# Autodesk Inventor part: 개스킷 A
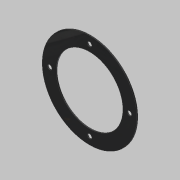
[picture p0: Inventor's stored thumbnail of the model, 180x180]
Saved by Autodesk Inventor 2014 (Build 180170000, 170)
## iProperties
Created: 2019-10
Part Number: 개스킷 A
Material: 고무
Document SubType Name: Modeling
Designer: mduedu
Density: 1 g/cm^3
Appearance: Rubber - Black - Version 1.1
Author: mduedu
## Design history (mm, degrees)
sketch "스케치1"
  geometry: C1 r 47.5 at (0, 0); C2 r 33.5 at (0, 0); 1 further point
  constraints: 2 centre point, 2 coincident
  dimensions: "d0" = 95 diameter of C1; "d1" = 67 diameter of C2
extrude "돌출1" new body sketch "스케치1" distance "d2" = 1; taper "d3" = 0 deg
sketch "스케치2" dims "d4" = 80
  geometry: C1 r 2.25 at (0, 40); 2 further points
  constraints: 2 vertical alignment, 1 centre point, 1 coincident, 2 other
  dimensions: "d5" = 4.5 diameter of C1
extrude "돌출2" cut sketch "스케치2" stored distance "d6" = 1; taper "d7" = 0 deg
node "솔리드1"
pattern_circular "원형 패턴1" dims angle "d9" = 360 deg
